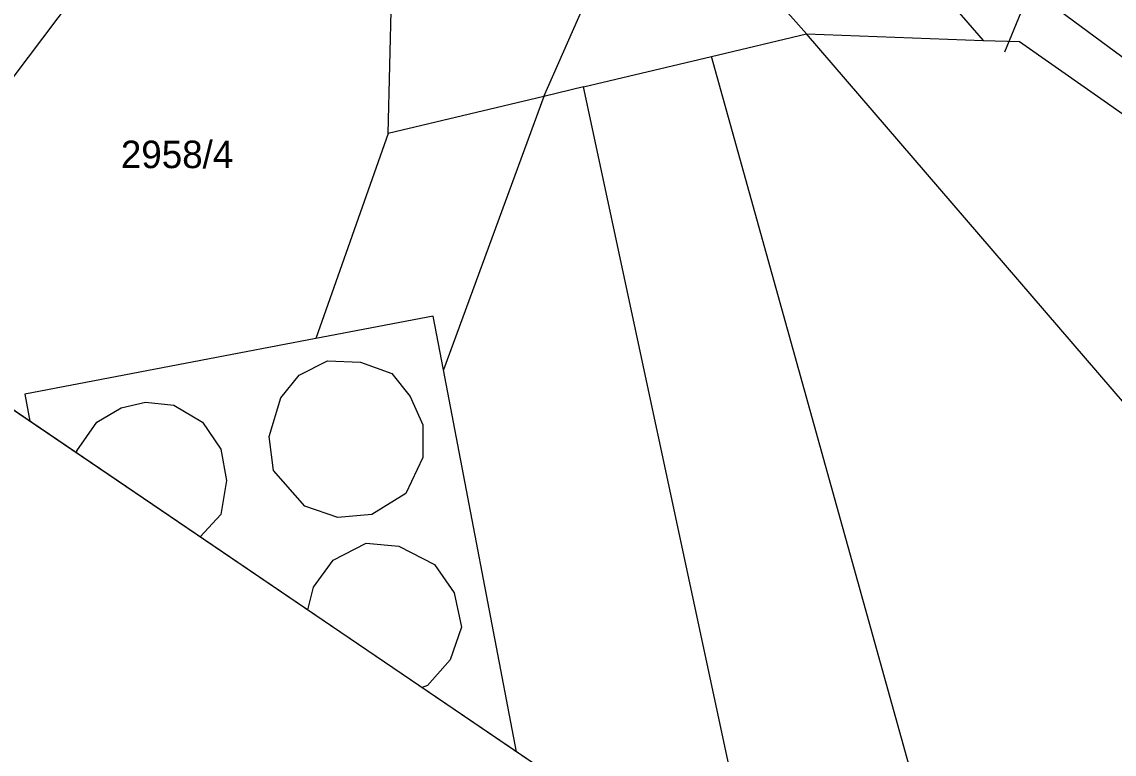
# Model space of a CAD drawing. Extents: x -621145 to -620110, y -1122807 to -1121971.
# Drawn here: x -620515.9 to -620456.4, y -1122662.4 to -1122622.5 of the extents above; entities that cross this region are included whole.
import ezdxf

# ---------------------------------------------------------------- set-up
doc = ezdxf.new("R2010")
doc.units = 0
for name, color, linetype in [('RÁMY', 7, 'Continuous'), ('VAS stoka', 7, 'Continuous'), ('VAS vodovod', 7, 'Continuous'), ('Vrstva 55', 7, 'Continuous'), ('Vrstva 56', 7, 'Continuous'), ('Vrstva 57', 7, 'Continuous')]:
    doc.layers.add(name, color=color, linetype=linetype)

msp = doc.modelspace()

# ---------------------------------------------------------------- linework, layer by layer
at = {"layer": 'RÁMY'}
for points in [[(-621061.558, -1122093.918), (-620192.937, -1122683.831), (-620276.367, -1122806.679), (-621144.989, -1122216.766)], [(-620887.834, -1122211.901), (-620192.937, -1122683.831), (-620276.367, -1122806.679), (-620971.264, -1122334.748)]]:
    msp.add_lwpolyline(points, close=True, dxfattribs=at)
at = {"layer": 'VAS stoka'}
msp.add_lwpolyline([(-620462.32, -1122624.12), (-620460.41, -1122619.475), (-620458.5, -1122614.83), (-620457.045, -1122611.605), (-620455.59, -1122608.38), (-620455.22, -1122607.205), (-620454.85, -1122606.03), (-620462.045, -1122599.785), (-620469.24, -1122593.54), (-620475.48, -1122588.525), (-620481.668, -1122583.552)], dxfattribs=at)
at = {"layer": 'VAS vodovod'}
msp.add_lwpolyline([(-620346.78, -1122722.2), (-620350.174, -1122711.617), (-620361.503, -1122697.496), (-620361.995, -1122696.756), (-620371.189, -1122688.51), (-620418.428, -1122648.878), (-620439.216, -1122636.741), (-620439.292, -1122636.689), (-620439.369, -1122636.637), (-620460.455, -1122621.063), (-620460.697, -1122620.904), (-620459.947, -1122619.769), (-620451.505, -1122607.786), (-620450.885, -1122606.963), (-620476.529, -1122586.081), (-620476.532, -1122586.079), (-620476.869, -1122585.61)], dxfattribs=at)
at = {"layer": 'Vrstva 55'}
for p, q in [((-620503.19, -1122607.95), (-620524.52, -1122636.25)), ((-620495.96, -1122628.58), (-620495.65, -1122615.65)), ((-620473.14, -1122623.15), (-620476.96, -1122618.82)), ((-620478.32, -1122624.38), (-620473.14, -1122623.15)), ((-620434.88, -1122667.63), (-620473.14, -1122623.15)), ((-620473.14, -1122623.15), (-620463.51, -1122623.5)), ((-620485.31, -1122626.04), (-620478.32, -1122624.38)), ((-620463.28, -1122678.3), (-620478.32, -1122624.38)), ((-620485.31, -1122626.04), (-620487.46, -1122626.56)), ((-620475.572, -1122671.392), (-620485.31, -1122626.04)), ((-620487.46, -1122626.56), (-620495.96, -1122628.58)), ((-620493.5, -1122638.55), (-620499.9, -1122639.77)), ((-620492.94, -1122641.47), (-620493.5, -1122638.55)), ((-620499.9, -1122639.77), (-620506.17, -1122640.97)), ((-620506.17, -1122640.97), (-620515.78, -1122642.8)), ((-620488.951, -1122662.306), (-620492.94, -1122641.47)), ((-620515.78, -1122642.8), (-620515.498, -1122644.276))]:
    msp.add_line(p, q, dxfattribs=at)
msp.add_lwpolyline([(-620463.51, -1122623.5), (-620461.53, -1122623.57), (-620450.04, -1122631.61)], dxfattribs=at)
at = {"layer": 'Vrstva 56'}
for p, q in [((-620487.46, -1122626.56), (-620480.79, -1122611.41)), ((-620471.33, -1122614.44), (-620463.51, -1122623.5)), ((-620487.46, -1122626.56), (-620492.94, -1122641.47)), ((-620495.96, -1122628.58), (-620499.9, -1122639.77)), ((-620500.81, -1122641.76), (-620499.26, -1122640.98)), ((-620499.26, -1122640.98), (-620497.47, -1122641.06)), ((-620497.47, -1122641.06), (-620495.76, -1122641.68)), ((-620501.82, -1122643), (-620500.81, -1122641.76)), ((-620495.76, -1122641.68), (-620494.75, -1122642.92)), ((-620510.52, -1122643.55), (-620509.2, -1122643.23)), ((-620509.2, -1122643.23), (-620507.65, -1122643.39)), ((-620502.44, -1122645.1), (-620501.82, -1122643)), ((-620494.75, -1122642.92), (-620494.06, -1122644.48)), ((-620511.84, -1122644.32), (-620510.52, -1122643.55)), ((-620507.65, -1122643.39), (-620506.09, -1122644.32)), ((-620512.93, -1122645.88), (-620511.84, -1122644.32)), ((-620506.09, -1122644.32), (-620505.08, -1122645.8)), ((-620494.06, -1122644.48), (-620494.06, -1122646.26)), ((-620502.21, -1122646.96), (-620502.44, -1122645.1)), ((-620512.935, -1122646.017), (-620512.93, -1122645.88)), ((-620505.08, -1122645.8), (-620504.77, -1122647.51)), ((-620494.06, -1122646.26), (-620494.99, -1122648.21)), ((-620504.77, -1122647.51), (-620505.08, -1122649.37)), ((-620500.5, -1122648.9), (-620502.21, -1122646.96)), ((-620494.99, -1122648.21), (-620496.85, -1122649.37)), ((-620498.71, -1122649.52), (-620500.5, -1122648.9)), ((-620505.08, -1122649.37), (-620506.22, -1122650.578)), ((-620496.85, -1122649.37), (-620498.71, -1122649.52)), ((-620498.95, -1122651.85), (-620497.16, -1122650.92)), ((-620497.16, -1122650.92), (-620495.38, -1122651.08)), ((-620495.38, -1122651.08), (-620493.43, -1122652.09)), ((-620500.03, -1122653.33), (-620498.95, -1122651.85)), ((-620493.43, -1122652.09), (-620492.35, -1122653.64)), ((-620500.343, -1122654.569), (-620500.03, -1122653.33)), ((-620492.35, -1122653.64), (-620491.96, -1122655.5)), ((-620491.96, -1122655.5), (-620492.58, -1122657.29)), ((-620492.58, -1122657.29), (-620493.82, -1122658.69)), ((-620493.82, -1122658.69), (-620494.104, -1122658.806))]:
    msp.add_line(p, q, dxfattribs=at)

# ---------------------------------------------------------------- texts
at = {"layer": 'Vrstva 57'}
msp.add_text('2958/4', height=1.5, dxfattribs=at).set_placement((-620510.538, -1122630.47))

doc.saveas('drawing.dxf')
